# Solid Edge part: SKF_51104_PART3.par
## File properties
Title: SKF_51104_PART3
Author: psAdmin
Comments: Thrust ball bearings, single direction
Template: iso metric part.par
Last saved by: psAdmin
Revision: 1
Application: Solid Edge
Document Number: SKF_51104_PART3
Company: SKF
Density: 2,31553201539e+04 kg/m^3
Accuracy: 0,990
NB: SKF_51104_PART3
NT: Thrust ball bearings, single direction
NBSYN: SKF_$TC._PART3
LINA: SKF_51104_PART3
CATALOG: SKF
DESIGNATION: 51104
WASHER: No seat washer
DD: 20.0
D: 35.0
H: 10.00
LOAD1: 15.1
LOAD2: 29.0
LOAD3: 1.1
SPEED1: 7500
SPEED2: 10000
BEARING: 51104
SUPPLIER: SKF
ARTICLENO: SKF_51104_PART3
BOMINFO: SKF_51104_PART3
CREATOR: CADENAS GmbH
ID: skf:SKF_51104_PART3
CADENASIDSTR: DOCATTR{IDENT{"{$CADENAS_DATA/23d-libs/skf/bearings_units_and_housings/ball_bearings/thrust_ball_bearings/bd1_001_bdc_001.prj},207 {VTYP=3D},{NB=SKF_51104_PART3},{LINA=SKF_51104_PART3},{NN=BD1_001_BDC_001_PART3},{NOPRJ=TRUE},{DATE=08.09.2023 08:50:36},{GEOMDATE=04.09.2023 08:34:44},{VERSION=},{LINEID=46530},{WBVAR=WASHER},{WBNUMERIC=}  {NB=SKF_51104_PART3},{LINA=SKF_51104_PART3},{KT=DUMMY},{DESIGNATION=51104},{WASHER=},{DD=20.0},{D=35.0},{DX=},{DXX=MIN},{H=10.00},{H1=},{DD1=35.00},{D1=21.00},{D2=},{D3=},{C=},{R=},{SS=},{R12=0.3},{PITCH=27.500},{DW=5.556},{ALPHA=90},{DAMIN=29.00},{DAMAX=26.00},{RAMAX=0.30},{LOAD1=15.1},{LOAD2=29.0},{LOAD3=1.1},{SPEED1=7500},{SPEED2=10000},{A=0.0044},{Z=14},{II=1},{MASS=0.03700},{BEARING=51104},{WASHERVAR=},{POPULAR=Yes},{XHO=7.2224},{BHO=2.7776},{BSH=2.7776},{Y3=0},{H3=0},{B3=0},{WASHERALG='','No seat washer'},{WSPN=},{DESIGN=tbb1},{H1ALG=0},{SSALG=0},{RALG=0},{TC=51104},{DXA=35.000}"}}
Username: psAdmin
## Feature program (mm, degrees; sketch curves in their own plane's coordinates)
sketch for "unnamed RevolvedProtrusion 1" plane through (0, 0, 0) normal (0, 0, 1) x-axis (1, 0, 0)
revolve "unnamed RevolvedProtrusion 1" add finite 360 deg about sketch line (9.7, 0) -> (7.2224, 0)
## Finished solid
Body 1: solid body, 8 faces, 8 edges, 0 vertices.
  Faces by surface: plane 3, torus 3, cylinder 2
  Edges by curve: circle 8
Bounding box of the edges (mm; curved faces can reach further): 2.778 x 35.000 x 35.000, from (7.2224, -17.5, -17.5) to (10, 17.5, 17.5).
Cylindrical faces by radius (mm): R10.5 x1, R17.5 x1
Toroidal faces (ring radius, tube radius in mm): R10.8 r0.3 x1, R13.75 r2.778 x1, R17.2 r0.3 x1
Planar faces by outward normal: +x 1, -x 2
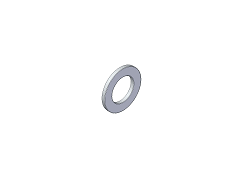
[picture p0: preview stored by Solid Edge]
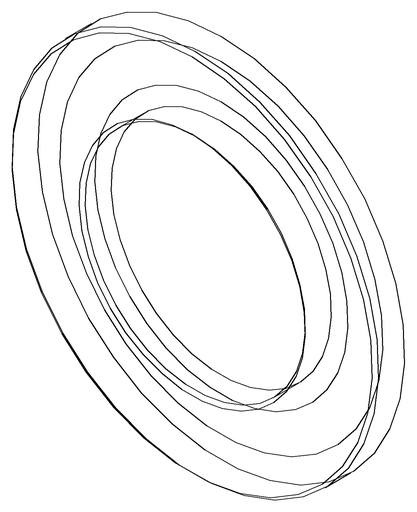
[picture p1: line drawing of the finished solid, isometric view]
